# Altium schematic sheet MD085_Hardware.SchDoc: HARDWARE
size 431 x 279 mm; Date: Not shown in title block; ApprovedBy: Not shown in title block; CheckedBy: Not shown in title block; Author: Not shown in title block; CompanyName: Not shown in title block; DrawnBy: Keerthi Kumanan; Engineer: Not shown in title block; Organization: Not shown in title block; Address1: Not shown in title block; Address2: Not shown in title block; Address3: Not shown in title block; Address4: Not shown in title block; DocumentNumber: 3; Revision: Use project parameter SCH_Rev; SheetNumber: 6; SheetTotal: 2; PageSetup: Record=PageOptions¦CenterHorizontal=True¦CenterVertical=True¦PrintScale=1.00¦XCorrection=1.00¦YCorrection=1.00¦PrintKind=0¦BorderSize=5000000¦LeftOffset=0¦BottomOffset=0¦Orientation=2¦PaperLength=1000¦PaperWidth=1000¦Scale=100¦PaperSource=15¦PrintQuality=600¦MediaType=1¦DitherType=10¦PaperKind=Letter¦PrintScaleMode=1
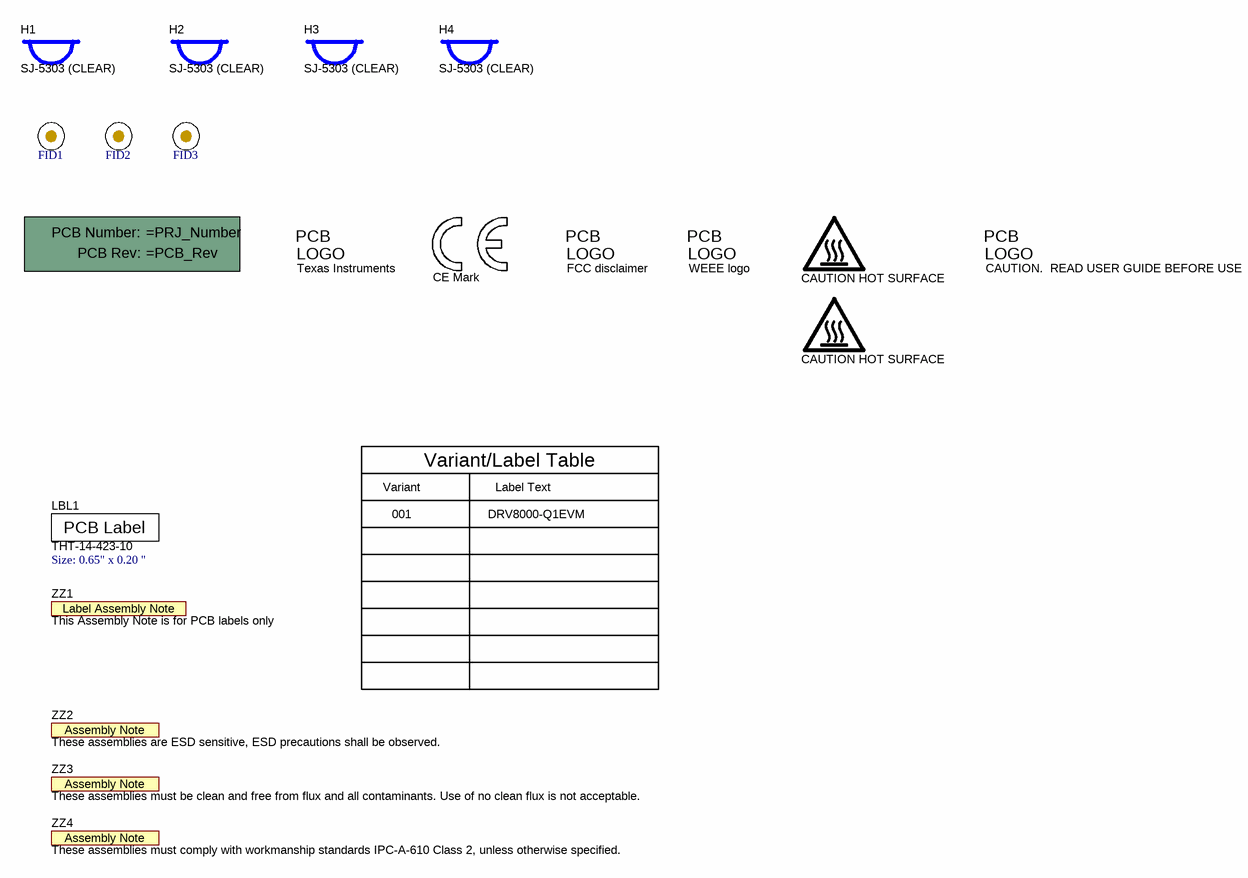
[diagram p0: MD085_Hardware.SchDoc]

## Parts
!PCB1  Printed Circuit Board  (value not drawn)  (mechanical)
FID1  Fiducial  [Fiducial10-20]  (value not drawn)
FID2  Fiducial  [Fiducial10-20]  (value not drawn)
FID3  Fiducial  [Fiducial10-20]  (value not drawn)
H1  SJ-5303 (CLEAR)  [Bumpon_SJ5003Transparent]
H2  SJ-5303 (CLEAR)  [Bumpon_SJ5003Transparent]
H3  SJ-5303 (CLEAR)  [Bumpon_SJ5003Transparent]
H4  SJ-5303 (CLEAR)  [Bumpon_SJ5003Transparent]
LBL1  THT-14-423-10  Note: Size: 0.65" x 0.20 "  [Label_650x200]
Logo1  CE Mark  [CE_Mark_5mm]  (no BOM)
Logo2  Texas Instruments  [TI_Stacked_Overlay_Small]  (no BOM)
Logo3  FCC disclaimer  [FCC_disclaimer]  (no BOM)
Logo4  WEEE logo  [WEEE_Minimum]  (no BOM)
LOGO5  CAUTION HOT SURFACE  [IEC_HotSurface_Small]  (no BOM)
Logo6  CAUTION.  READ USER GUIDE BEFORE USE  [IEC_Caution_Small]  (no BOM)
LOGO7  CAUTION HOT SURFACE  [IEC_HotSurface_Small]  (no BOM)
ZZ1  This Assembly Note is for PCB labels only  [AssemblyNoteLabel]  (no BOM)
ZZ2  These assemblies are ESD sensitive, ESD precautions shall be observed.  [AssemblyNote]  (no BOM)
ZZ3  These assemblies must be clean and free from flux and all contaminants. Use of no clean flux is not acceptable.  [AssemblyNote]  (no BOM)
ZZ4  These assemblies must comply with workmanship standards IPC-A-610 Class 2, unless otherwise specified.  [AssemblyNote]  (no BOM)

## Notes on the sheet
- Variant
- Variant/Label Table
- Label Text
- 001
- DRV8000-Q1EVM

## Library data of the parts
!PCB1 = CMP-0003618-2: Manufacturer: Any
FID1-FID3 = CMP-0077181-1: Fiducial mark.  There is nothing to buy or mount.
H1-H4 = CMP-0003620-1: Bumpon, Hemisphere, 0.44 X 0.20, Clear; Manufacturer: 3M
LBL1 = CMP-0003625-1: Thermal Transfer Printable Labels, 0.650" W x 0.200" H - 10,000 per roll; Manufacturer: Brady
Logo1 = CMP-0074844-1: SymbolCreator: a0412235
Logo2 = CMP-0074838-1: Texas Instrument Corporate Signature; SymbolCreator: a0412235; Lib Reference: TI_Logo
Logo3 = CMP-0074847-1: FCC_disclaimer
Logo4 = CMP-0074769-3: Manufacturer: Texas Instruments; AEC Category: Q200; CompType: IC
LOGO5 LOGO7 = CMP-0074837-2: IEC 61010-1 Hot Surface Warning; Manufacturer: Texas Instruments; SymbolCreator: a0412235; CompType: IC; AEC Category: Q200
Logo6 = CMP-0074836-1: IEC 61010-1 Caution Warning; SymbolCreator: a0412235; Lib Reference: IEC_Caution
ZZ1 = CMP-0003616-3
ZZ2 = CMP-0077236-1
ZZ3 = CMP-0077237-1
ZZ4 = CMP-0077238-1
